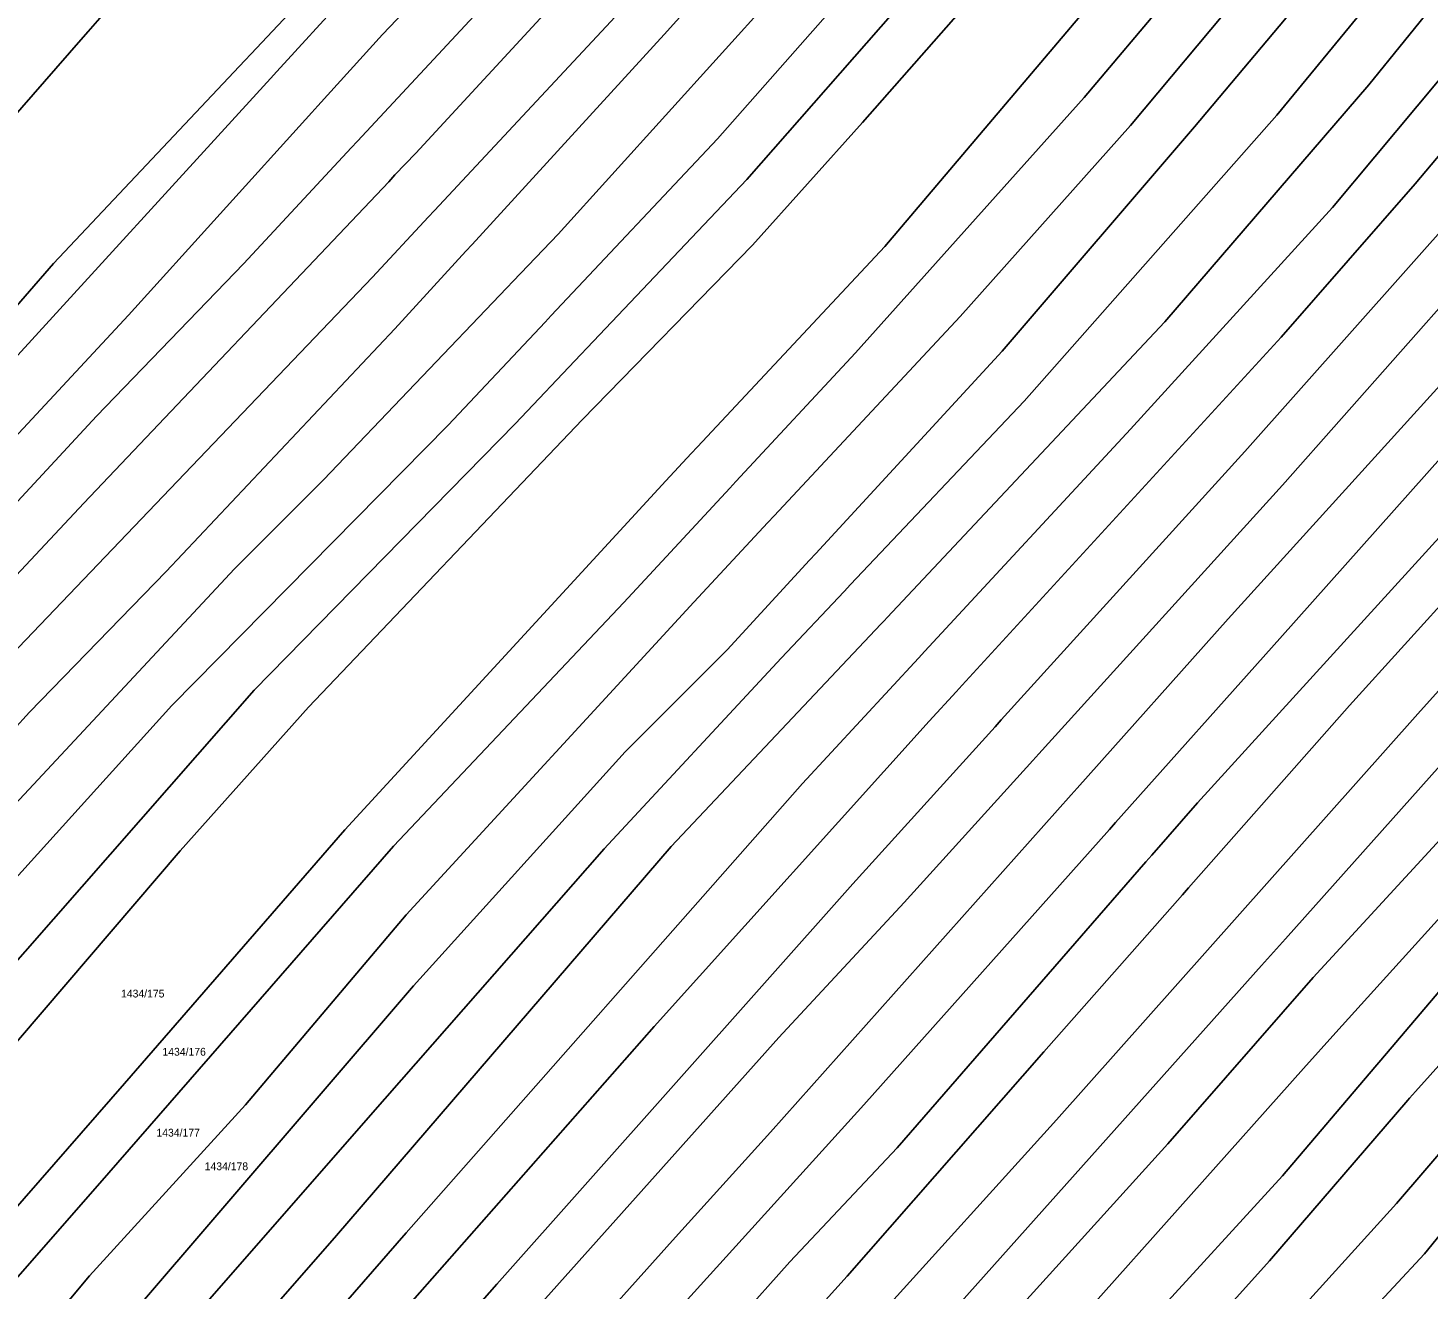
# Model space of a CAD drawing. Extents: x -580630 to -576196, y -1189024 to -1183567.
# Drawn here: x -578693.1 to -578387.5, y -1186653.5 to -1186378.2 of the extents above; entities that cross this region are included whole.
import ezdxf

# ---------------------------------------------------------------- set-up
doc = ezdxf.new("R2010")
doc.units = 0
for name, color, linetype in [('Vrstva 1', 7, 'Continuous'), ('Vrstva 18', 7, 'Continuous'), ('Vrstva 6', 7, 'Continuous')]:
    doc.layers.add(name, color=color, linetype=linetype)

msp = doc.modelspace()

# ---------------------------------------------------------------- linework, layer by layer
at = {"layer": 'Vrstva 1'}
for p, q in [((-578679.95, -1186378.95), (-578526.08, -1186202.72)), ((-578638.8, -1186387.71), (-578616.07, -1186362.82)), ((-578628.65, -1186367.11), (-578644.37, -1186383.81)), ((-578681.56, -1186380.79), (-578679.95, -1186378.95)), ((-578739.65, -1186447.33), (-578681.56, -1186380.79)), ((-578645.76, -1186385.28), (-578687.52, -1186429.64)), ((-578644.37, -1186383.81), (-578645.76, -1186385.28)), ((-578640.16, -1186389.2), (-578638.8, -1186387.71)), ((-578699.21, -1186453.87), (-578640.16, -1186389.2)), ((-578687.52, -1186429.64), (-578706.12, -1186450.96))]:
    msp.add_line(p, q, dxfattribs=at)
at = {"layer": 'Vrstva 6'}
for p, q in [((-578380.99, -1186296.39), (-578462.55, -1186393.38)), ((-578364.3, -1186311.26), (-578438.47, -1186399.77)), ((-578494.87, -1186313.89), (-578554.23, -1186379.6)), ((-578525.33, -1186315.4), (-578608.45, -1186405.52)), ((-578558.23, -1186319.43), (-578615.7, -1186379.59)), ((-578420.54, -1186397.21), (-578355.95, -1186318.55)), ((-578506.09, -1186425.91), (-578421.4, -1186325.97)), ((-578348.41, -1186326.38), (-578400.47, -1186390.62)), ((-578536.19, -1186411.3), (-578464.28, -1186329.29)), ((-578452.49, -1186399.47), (-578394.27, -1186329.93)), ((-578408.34, -1186417.4), (-578340.22, -1186335.64)), ((-578621.18, -1186402.92), (-578562.12, -1186339.31)), ((-578486.62, -1186338.88), (-578542.62, -1186402.43)), ((-578604.35, -1186418.04), (-578535.33, -1186343.95)), ((-578577.35, -1186423.18), (-578505.75, -1186343.92)), ((-578334.15, -1186345.35), (-578390.36, -1186412.21)), ((-578465.55, -1186347.11), (-578510.93, -1186398.85)), ((-578615.7, -1186379.59), (-578629.8, -1186395.17)), ((-578554.23, -1186379.6), (-578596.13, -1186425.43)), ((-578400.47, -1186390.62), (-578444.94, -1186442.34)), ((-578462.55, -1186393.38), (-578512.51, -1186449.11)), ((-578631.14, -1186396.66), (-578671.17, -1186440.89)), ((-578629.8, -1186395.17), (-578631.14, -1186396.66)), ((-578475.66, -1186459.65), (-578420.54, -1186397.21)), ((-578427.48, -1186470.63), (-578362.02, -1186396.95)), ((-578510.93, -1186398.85), (-578534.97, -1186425.64)), ((-578489.63, -1186441.15), (-578452.49, -1186399.47)), ((-578438.47, -1186399.77), (-578480.48, -1186448.76)), ((-578622.55, -1186404.39), (-578621.18, -1186402.92)), ((-578542.62, -1186402.43), (-578578.87, -1186440.94)), ((-578645.94, -1186429.58), (-578622.55, -1186404.39)), ((-578608.45, -1186405.52), (-578612.98, -1186410.29)), ((-578614.36, -1186411.75), (-578680.91, -1186481.9)), ((-578612.98, -1186410.29), (-578614.36, -1186411.75)), ((-578571.02, -1186448), (-578536.19, -1186411.3)), ((-578390.36, -1186412.21), (-578419.6, -1186445.68)), ((-578605.71, -1186419.51), (-578604.35, -1186418.04)), ((-578452.48, -1186465.76), (-578408.34, -1186417.4)), ((-578617.88, -1186432.57), (-578605.71, -1186419.51)), ((-578587.18, -1186433.48), (-578577.35, -1186423.18)), ((-578597.49, -1186426.91), (-578612.98, -1186443.85)), ((-578596.13, -1186425.43), (-578597.49, -1186426.91)), ((-578534.97, -1186425.64), (-578572.16, -1186463.76)), ((-578546.96, -1186469.64), (-578506.09, -1186425.91)), ((-578372.69, -1186425.32), (-578419.27, -1186477.97)), ((-578678.13, -1186462.97), (-578645.94, -1186429.58)), ((-578703.77, -1186522.43), (-578617.88, -1186432.57)), ((-578588.56, -1186434.93), (-578587.18, -1186433.48)), ((-578431.13, -1186507.18), (-578363.85, -1186432.93)), ((-578628.56, -1186476.85), (-578588.56, -1186434.93)), ((-578671.17, -1186440.89), (-578706.79, -1186479.2)), ((-578580.24, -1186442.4), (-578601.4, -1186464.88)), ((-578578.87, -1186440.94), (-578580.24, -1186442.4)), ((-578530.23, -1186484.7), (-578489.63, -1186441.15)), ((-578444.94, -1186442.34), (-578505.55, -1186506.91)), ((-578612.98, -1186443.85), (-578662.91, -1186496.85)), ((-578419.6, -1186445.68), (-578489.16, -1186521.63)), ((-578586.75, -1186464.58), (-578572.4, -1186449.45)), ((-578572.4, -1186449.45), (-578571.02, -1186448)), ((-578512.51, -1186449.11), (-578538.57, -1186477.2)), ((-578480.48, -1186448.76), (-578521.12, -1186492.9)), ((-578363.85, -1186448.48), (-578419.88, -1186511.49)), ((-578513.54, -1186499.72), (-578475.66, -1186459.65)), ((-578758.6, -1186549.59), (-578678.13, -1186462.97)), ((-578643.7, -1186522.74), (-578586.75, -1186464.58)), ((-578572.16, -1186463.76), (-578631.84, -1186526.46)), ((-578389.72, -1186527.92), (-578333.07, -1186464.58)), ((-578601.4, -1186464.88), (-578661.7, -1186526.11)), ((-578497.35, -1186514.27), (-578452.48, -1186465.76)), ((-578349.57, -1186465.23), (-578404.68, -1186526.12)), ((-578548.33, -1186471.11), (-578546.96, -1186469.64)), ((-578480.65, -1186529.26), (-578427.48, -1186470.63)), ((-578553.88, -1186477.05), (-578548.33, -1186471.11)), ((-578648.02, -1186496.28), (-578628.56, -1186476.85)), ((-578623.94, -1186553.22), (-578553.88, -1186477.05)), ((-578539.93, -1186478.67), (-578563.05, -1186503.59)), ((-578538.57, -1186477.2), (-578539.93, -1186478.67)), ((-578419.27, -1186477.97), (-578472.43, -1186536.64)), ((-578680.91, -1186481.9), (-578707.13, -1186509.96)), ((-578437.85, -1186547.32), (-578379.09, -1186482.82)), ((-578547.79, -1186503.55), (-578531.59, -1186486.17)), ((-578531.59, -1186486.17), (-578530.23, -1186484.7)), ((-578335.5, -1186483.8), (-578418.65, -1186577.01)), ((-578522.48, -1186494.38), (-578540.48, -1186513.93)), ((-578521.12, -1186492.9), (-578522.48, -1186494.38)), ((-578710.76, -1186563.6), (-578648.02, -1186496.28)), ((-578662.91, -1186496.85), (-578692.74, -1186527.57)), ((-578528.7, -1186515.76), (-578514.92, -1186501.18)), ((-578514.92, -1186501.18), (-578513.54, -1186499.72)), ((-578563.05, -1186503.59), (-578613.27, -1186556.84)), ((-578610.52, -1186571.78), (-578547.79, -1186503.55)), ((-578505.55, -1186506.91), (-578506.2, -1186507.61)), ((-578464.07, -1186544.14), (-578431.13, -1186507.18)), ((-578506.92, -1186508.37), (-578552.68, -1186556.85)), ((-578506.2, -1186507.61), (-578506.92, -1186508.37)), ((-578419.88, -1186511.49), (-578455.7, -1186551.65)), ((-578567.34, -1186557.41), (-578528.7, -1186515.76)), ((-578540.48, -1186513.93), (-578562.73, -1186536.2)), ((-578524.06, -1186543.14), (-578498.71, -1186515.74)), ((-578498.71, -1186515.74), (-578497.35, -1186514.27)), ((-578412.58, -1186585.46), (-578350.13, -1186517.51)), ((-578714.67, -1186603.74), (-578643.7, -1186522.74)), ((-578489.16, -1186521.63), (-578490.51, -1186523.11)), ((-578337.98, -1186520.35), (-578406.28, -1186595.98)), ((-578490.51, -1186523.11), (-578496.41, -1186529.55)), ((-578692.74, -1186527.57), (-578737.24, -1186576.37)), ((-578661.7, -1186526.11), (-578716.21, -1186586.4)), ((-578631.84, -1186526.46), (-578659.85, -1186557.82)), ((-578468.61, -1186616.55), (-578389.72, -1186527.92)), ((-578404.68, -1186526.12), (-578439.8, -1186565.91)), ((-578496.41, -1186529.55), (-578556.39, -1186596.18)), ((-578513.06, -1186565), (-578482, -1186530.75)), ((-578482, -1186530.75), (-578480.65, -1186529.26)), ((-578562.73, -1186536.2), (-578608.97, -1186587.29)), ((-578473.77, -1186538.13), (-578501.84, -1186569.11)), ((-578472.43, -1186536.64), (-578473.77, -1186538.13)), ((-578610.55, -1186641.19), (-578524.06, -1186543.14)), ((-578465.41, -1186545.64), (-578464.07, -1186544.14)), ((-578531.04, -1186619.27), (-578465.41, -1186545.64)), ((-578447.79, -1186558.75), (-578437.85, -1186547.32)), ((-578672.02, -1186608.63), (-578623.94, -1186553.22)), ((-578457.03, -1186553.15), (-578510.66, -1186613.28)), ((-578455.7, -1186551.65), (-578457.03, -1186553.15)), ((-578340.05, -1186554.15), (-578390.24, -1186610.37)), ((-578659.85, -1186557.82), (-578723.2, -1186631.83)), ((-578613.27, -1186556.84), (-578677.89, -1186630.96)), ((-578552.68, -1186556.85), (-578625.77, -1186641.84)), ((-578615.19, -1186612), (-578567.34, -1186557.41)), ((-578449.11, -1186560.26), (-578447.79, -1186558.75)), ((-578503.39, -1186622.65), (-578449.11, -1186560.26)), ((-578590.74, -1186652.44), (-578513.06, -1186565)), ((-578441.13, -1186567.41), (-578471.38, -1186601.68)), ((-578439.8, -1186565.91), (-578441.13, -1186567.41)), ((-578501.84, -1186569.11), (-578529.2, -1186598.59)), ((-578645.58, -1186613.25), (-578610.52, -1186571.78)), ((-578418.65, -1186577.01), (-578422.55, -1186581.38)), ((-578397.86, -1186603.53), (-578373.58, -1186574.89)), ((-578423.89, -1186582.87), (-578512.46, -1186682.08)), ((-578422.55, -1186581.38), (-578423.89, -1186582.87)), ((-578444.28, -1186621.76), (-578412.58, -1186585.46)), ((-578608.97, -1186587.29), (-578671.15, -1186659.87)), ((-578556.39, -1186596.18), (-578631.3, -1186681.11)), ((-578406.28, -1186595.98), (-578407.62, -1186597.46)), ((-578529.2, -1186598.59), (-578588.31, -1186664.67)), ((-578407.62, -1186597.46), (-578414.73, -1186605.33)), ((-578471.38, -1186601.68), (-578514.29, -1186650.67)), ((-578414.73, -1186605.33), (-578493.91, -1186694.24)), ((-578419.26, -1186628.77), (-578399.15, -1186605.06)), ((-578399.15, -1186605.06), (-578397.86, -1186603.53)), ((-578749.69, -1186697.61), (-578672.02, -1186608.63)), ((-578390.24, -1186610.37), (-578391.57, -1186611.86)), ((-578679.62, -1186650.61), (-578645.58, -1186613.25)), ((-578679.1, -1186684.99), (-578615.19, -1186612)), ((-578510.66, -1186613.28), (-578569.11, -1186677.83)), ((-578391.94, -1186612.27), (-578422.12, -1186647.35)), ((-578391.57, -1186611.86), (-578391.94, -1186612.27)), ((-578561.79, -1186719.48), (-578468.61, -1186616.55)), ((-578363.33, -1186615.06), (-578388.28, -1186645.79)), ((-578551.77, -1186642.15), (-578531.04, -1186619.27)), ((-578394.37, -1186634.8), (-578382.03, -1186620.43)), ((-578526.83, -1186647.57), (-578503.39, -1186622.65)), ((-578508.49, -1186692.64), (-578444.28, -1186621.76)), ((-578465.22, -1186678.96), (-578419.26, -1186628.77)), ((-578677.89, -1186630.96), (-578733.9, -1186694.89)), ((-578481.45, -1186730.72), (-578394.37, -1186634.8)), ((-578625.77, -1186641.84), (-578695.52, -1186721.33)), ((-578686.07, -1186727.98), (-578610.55, -1186641.19)), ((-578626.36, -1186725.54), (-578551.77, -1186642.15)), ((-578619.44, -1186751.16), (-578526.83, -1186647.57)), ((-578422.12, -1186647.35), (-578497.63, -1186730.77)), ((-578388.28, -1186645.79), (-578430.26, -1186690.82)), ((-578739.97, -1186722.28), (-578679.62, -1186650.61)), ((-578514.29, -1186650.67), (-578549.61, -1186689.65)), ((-578644.09, -1186712.83), (-578590.74, -1186652.44))]:
    msp.add_line(p, q, dxfattribs=at)

# ---------------------------------------------------------------- texts
at = {"layer": 'Vrstva 18'}
for s, p in [('1434/175', (-578672.769, -1186589.84)), ('1434/176', (-578663.732, -1186602.54)), ('1434/177', (-578665.042, -1186620.21)), ('1434/178', (-578654.512, -1186627.55))]:
    msp.add_text(s, height=1.7, dxfattribs=at).set_placement(p)

doc.saveas('drawing.dxf')
